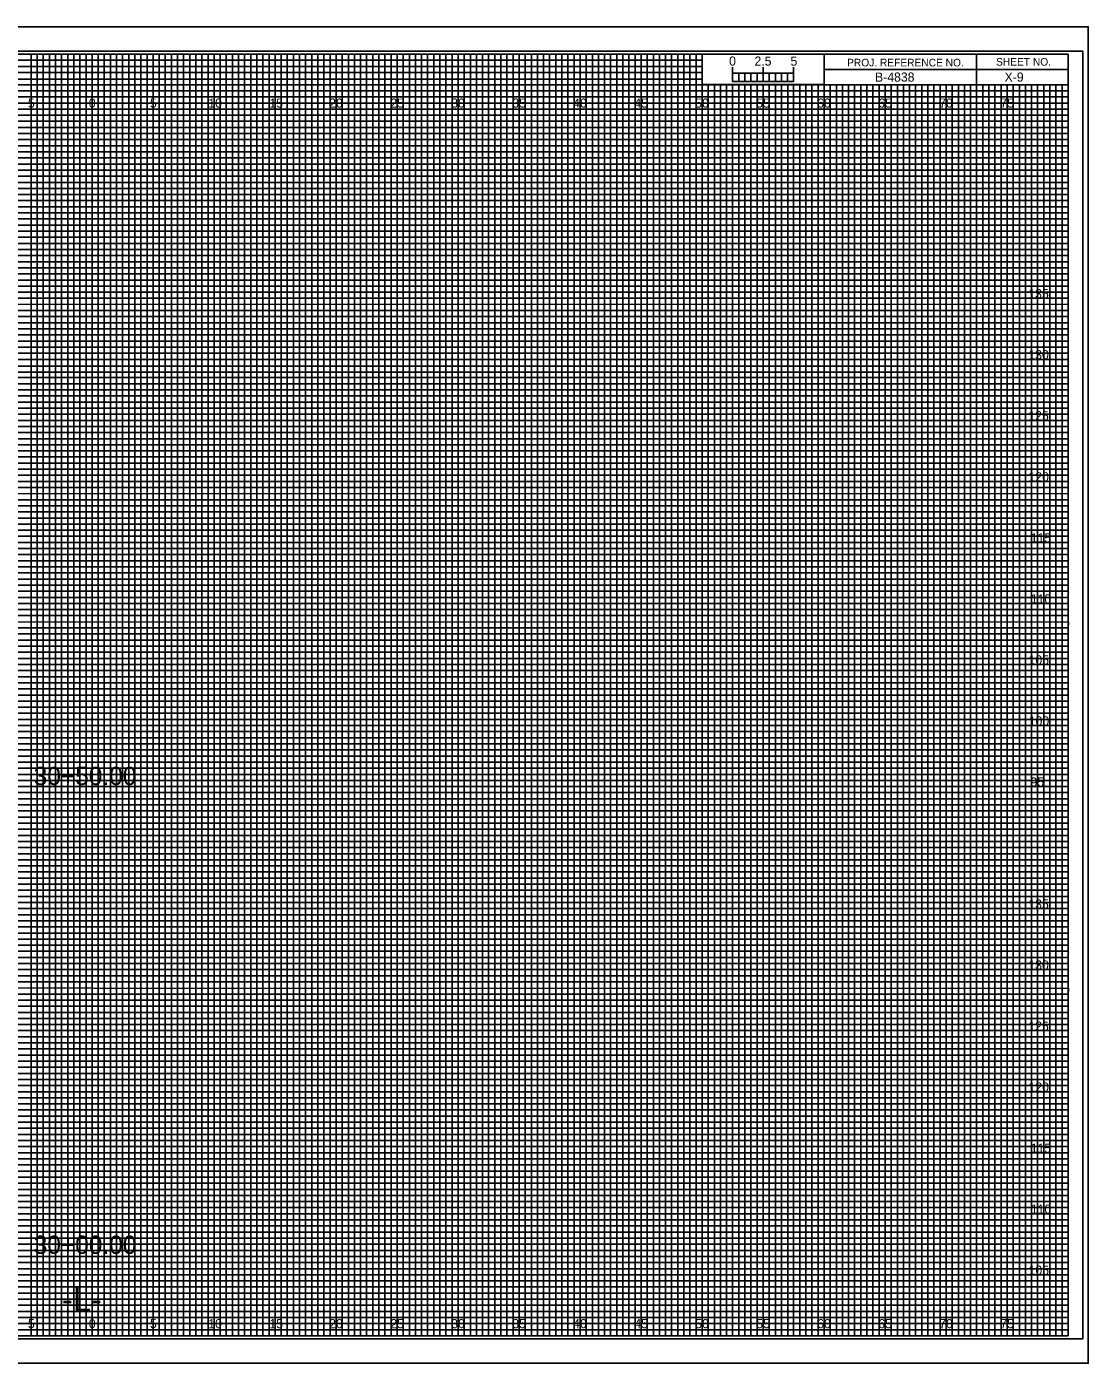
# Model space of a CAD drawing. Extents: x -7 to 182, y -2 to 1647.
# Drawn here: x 74.6 to 161.7, y 767.8 to 877.2 of the extents above; entities that cross this region are included whole.
import ezdxf

# ---------------------------------------------------------------- set-up
doc = ezdxf.new("R2010")
doc.units = 0
for name, color, linetype in [('Exist CMT Pavement', 7, 'Continuous'), ('Exist Cross Section Cell', 7, 'Continuous'), ('Exist XS Ground Line', 7, 'Continuous'), ('Prop CMT Pvmt Course 1', 7, 'Continuous'), ('Prop CMT Pvmt Course 2', 7, 'Continuous'), ('Prop CMT Pvmt Course 2 Wedge', 7, 'Continuous'), ('Prop CMT Pvmt Course 3', 7, 'Continuous'), ('Prop CMT Pvmt Surface', 7, 'Continuous'), ('Prop CMT Pvmt Surface Shoulder', 7, 'Continuous'), ('Prop CMT Pvmt Wedge Surface 1', 7, 'Continuous'), ('Prop CMT Pvmt Wedge Surface 2', 7, 'Continuous'), ('Prop CMT Pvmt Wedge Surface 3', 7, 'Continuous'), ('Prop CMT Shld Paved Course 1', 7, 'Continuous'), ('Prop CMT Shld Paved Course 2', 7, 'Continuous'), ('Prop CMT Shld Paved Course 3', 7, 'Continuous'), ('Prop CMT Slope Grass', 7, 'Continuous'), ('Prop CMT Subgrade Earthwork', 7, 'Continuous')]:
    doc.layers.add(name, color=color, linetype=linetype)

msp = doc.modelspace()

# ---------------------------------------------------------------- linework, layer by layer
at = {"layer": 'Exist XS Ground Line'}
for p, q in [((75, 875), (70, 875)), ((75, 770), (75, 875)), ((85, 875), (80, 875)), ((80, 875), (80, 770)), ((85, 770), (85, 875)), ((95, 875), (90, 875)), ((90, 875), (90, 770)), ((95, 770), (95, 875)), ((105, 875), (100, 875)), ((100, 875), (100, 770)), ((105, 770), (105, 875)), ((115, 875), (110, 875)), ((110, 875), (110, 770)), ((115, 770), (115, 875)), ((125, 875), (120, 875)), ((120, 875), (120, 770)), ((125, 770), (125, 875)), ((130, 875), (130, 770)), ((135, 770), (135, 872.5)), ((145, 872.5), (140, 872.5)), ((140, 872.5), (140, 770)), ((145, 770), (145, 872.5)), ((155, 872.5), (150, 872.5)), ((150, 872.5), (150, 770)), ((155, 770), (155, 872.5)), ((80, 770), (75, 770)), ((90, 770), (85, 770)), ((100, 770), (95, 770)), ((110, 770), (105, 770)), ((120, 770), (115, 770)), ((130, 770), (125, 770)), ((140, 770), (135, 770)), ((150, 770), (145, 770)), ((160, 770), (155, 770)), ((160, 770), (160, 770))]:
    msp.add_line(p, q, dxfattribs=at)
for points in [[(0, 870), (160, 870), (160, 865), (0, 865)], [(0, 860), (160, 860), (160, 855), (0, 855)], [(0, 850), (160, 850), (160, 845), (0, 845)], [(0, 840), (160, 840), (160, 835), (0, 835)], [(0, 830), (160, 830), (160, 825), (0, 825)], [(0, 820), (160, 820), (160, 815), (0, 815)], [(0, 810), (160, 810), (160, 805), (0, 805)], [(0, 800), (160, 800), (160, 795), (0, 795)], [(0, 790), (160, 790), (160, 785), (0, 785)], [(0, 780), (160, 780), (160, 775), (0, 775)]]:
    msp.add_lwpolyline(points, dxfattribs=at)
at = {"layer": 'Prop CMT Pvmt Course 2'}
for p, q in [((132.5, 872.75), (132.5, 873.95)), ((132.5, 873.45), (132.5, 873.95)), ((135, 872.75), (135, 873.95)), ((137.5, 872.75), (137.5, 873.95)), ((137.5, 873.45), (137.5, 873.95))]:
    msp.add_line(p, q, dxfattribs=at)
for points in [[(137.5, 873.45), (132.5, 873.45), (132.5, 872.75), (137.5, 872.75)], [(132.5, 873.45), (133, 873.45), (133, 872.75), (132.5, 872.75)], [(133.5, 873.45), (134, 873.45), (134, 872.75), (133.5, 872.75)], [(134.5, 873.45), (135, 873.45), (135, 872.75), (134.5, 872.75)], [(135.5, 873.45), (136, 873.45), (136, 872.75), (135.5, 872.75)], [(136.5, 873.45), (137, 873.45), (137, 872.75), (136.5, 872.75)]]:
    msp.add_lwpolyline(points, close=True, dxfattribs=at)
at = {"layer": 'Prop CMT Pvmt Course 3'}
msp.add_lwpolyline([(-6.7, 767.75), (161.65, 767.75), (161.65, 877.25), (-6.7, 877.25)], close=True, dxfattribs=at)
at = {"layer": 'Prop CMT Pvmt Wedge Surface 1'}
for p, q in [((0, 874.5), (130, 874.5)), ((130, 873.99), (0, 873.99)), ((130, 874.5), (130, 873.99)), ((0, 873.5), (130, 873.5)), ((130, 872.95), (0, 872.95)), ((130, 873.5), (130, 872.95)), ((0, 872), (160, 872))]:
    msp.add_line(p, q, dxfattribs=at)
for points in [[(0, 871.5), (135, 871.5), (160, 871.5), (160, 871), (0, 871)], [(0, 870.5), (160, 870.5), (160, 869.5), (0, 869.5)], [(0, 869), (160, 869), (160, 868.5), (0, 868.49)], [(0, 868), (160, 868), (160, 867), (0, 867)], [(0, 866.5), (160, 866.5), (160, 866), (0, 866)], [(0, 865.5), (160, 865.5), (160, 864.5), (0, 864.5)], [(0, 864), (160, 864), (160, 863.5), (0, 863.5)], [(0, 863), (160, 863), (160, 862), (0, 862)], [(0, 861.5), (160, 861.5), (160, 861), (0, 861)], [(0, 860.5), (160, 860.5), (160, 859.5), (0, 859.5)], [(0, 859), (160, 859), (160, 858.5), (0, 858.5)], [(0, 858), (160, 858), (160, 856.98), (160, 856.5), (160, 856), (0, 856)], [(0, 857), (160, 857), (160, 856.5), (0, 856.5)], [(0, 855.5), (160, 855.5), (160, 854.5), (0, 854.51)], [(0, 854.51), (160, 854.5), (160, 854), (0, 854)], [(0, 853.5), (160, 853.5), (160, 853), (0, 853)], [(0, 852), (160, 852), (160, 851.5), (0, 851.5)], [(0, 851), (160, 851), (160, 850.5), (0, 850.5)], [(-0.04, 849.45), (160, 849.45), (160, 848.94), (-0.04, 848.94)], [(0, 848.5), (160, 848.5), (160, 848), (0, 848)], [(0, 847), (160, 847), (160, 846.5), (0, 846.5)], [(0, 846), (160, 846), (160, 845.5), (0, 845.5)], [(0, 844.5), (160, 844.5), (160, 844), (0, 844)], [(0, 843.5), (160, 843.5), (160, 843), (0, 843)], [(0, 842), (160, 842), (160, 841.5), (0, 841.5)], [(0, 841), (160, 841), (160, 840.5), (0, 840.5)], [(0, 839.5), (160, 839.5), (160, 838.99), (0, 839)], [(0, 838.5), (160, 838.5), (160, 838), (0, 838)], [(0, 837), (160, 837), (160, 836.5), (0, 836.5)], [(0, 836), (160, 836), (160, 835.5), (0, 835.5)], [(0, 834.5), (160, 834.5), (160, 834), (0, 834)], [(0, 833.5), (160, 833.5), (160, 833), (0, 833)], [(0, 832), (160, 832), (160, 831.5), (0, 831.5)], [(0, 831), (160, 831), (160, 830.5), (0, 830.5)], [(0, 829.5), (160, 829.5), (160, 829), (0, 829)], [(0, 828.5), (160.03, 828.46), (160, 828), (0, 828)], [(0, 827), (160, 827), (160, 826.5), (0, 826.5)], [(0, 826), (160, 826), (160, 825.5), (0, 825.5)], [(0, 824.5), (160, 824.5), (160, 824), (0, 824)], [(0, 823.5), (160, 823.5), (160, 823), (0, 823)], [(0, 822), (160, 822), (160, 821.5), (0, 821.5)], [(0, 821), (160, 821), (160, 820.5), (0, 820.5)], [(0, 819.5), (160, 819.5), (160, 819), (0, 819)], [(0, 818.5), (160, 818.5), (160, 818), (0, 818)], [(0, 817), (160, 817), (160, 816.5), (0, 816.5)], [(0, 816), (160, 816), (160, 815.5), (0, 815.5)], [(0, 814.5), (160, 814.5), (160, 814), (0, 814)], [(0, 813.5), (160, 813.5), (160, 813), (0, 813)], [(0, 812), (160, 812), (160, 811.5), (0, 811.5)], [(0, 811), (160, 811), (160, 810.5), (0, 810.5)], [(0, 809.5), (160, 809.5), (160, 808.99), (0, 809)], [(0, 808.5), (160, 808.5), (160, 808), (0, 808)], [(0, 807), (160, 807), (160, 806.5), (0, 806.5)], [(0, 806), (160, 806), (160, 805.5), (0, 805.5)], [(0, 804.5), (160, 804.5), (160, 804), (0, 804)], [(0, 803.5), (160, 803.5), (160, 803), (0, 803)], [(0, 802), (160, 802), (160, 801.5), (0, 801.5)], [(0, 801), (160, 801), (160, 800.5), (0, 800.5)], [(0, 799.5), (160, 799.5), (160, 799), (0, 799)], [(0, 798.5), (160.03, 798.46), (160, 798), (0, 798)], [(0, 797), (160, 797), (160, 796.5), (0, 796.5)], [(0, 796), (160, 796), (160, 795.5), (0, 795.5)], [(0, 794.5), (160, 794.5), (160, 794), (0, 794)], [(0, 793.5), (160, 793.5), (160, 793), (0, 793)], [(0, 792), (160, 792), (160, 791.5), (0, 791.5)], [(0, 791), (160, 791), (160, 790.5), (0, 790.5)], [(0, 789.5), (160, 789.5), (160, 789), (0, 789)], [(0, 788.5), (160, 788.5), (160, 788), (0, 788)], [(0, 787), (160, 787), (160, 786.5), (0, 786.5)], [(0, 786), (160, 786), (160, 785.5), (0, 785.5)], [(0, 784.5), (160, 784.5), (160, 784), (0, 784)], [(0, 783.5), (160, 783.5), (160, 783), (0, 783)], [(0, 782), (160, 782), (160, 781.5), (0, 781.5)], [(0, 781), (160, 781), (160, 780.5), (0, 780.5)], [(0, 779.5), (160, 779.5), (160, 779), (0, 779)], [(0, 778.5), (160, 778.5), (160, 778), (0, 778)], [(0, 777), (160, 777), (160, 776.5), (0, 776.5)], [(0, 776), (160, 776), (160, 775.5), (0, 775.5)], [(0, 774.5), (160, 774.5), (160, 774), (0, 774)], [(0, 773.5), (160, 773.5), (160, 773), (0, 773)], [(0, 772), (160, 772), (160, 771.5), (0, 771.5)], [(0, 771), (160, 771), (160, 770.5), (0, 770.5)]]:
    msp.add_lwpolyline(points, dxfattribs=at)
at = {"layer": 'Prop CMT Pvmt Wedge Surface 2'}
for p, q in [((152.5, 875), (152.5, 872.5)), ((152.5, 872.5), (152.5, 875)), ((160, 873.75), (140, 873.75)), ((140, 873.75), (140, 872.5)), ((140, 872.5), (160, 872.5))]:
    msp.add_line(p, q, dxfattribs=at)
for points in [[(160, 875), (0, 875), (0, 770), (160, 770)], [(140, 875), (130, 875), (130, 872.51), (140, 872.51)], [(160, 875), (140, 875), (140, 872.5), (160, 872.5)]]:
    msp.add_lwpolyline(points, close=True, dxfattribs=at)
at = {"layer": 'Prop CMT Pvmt Wedge Surface 3'}
for p, q in [((133.5, 872.5), (133, 872.5)), ((133, 872.5), (133, 770)), ((133.5, 770), (133.5, 872.5)), ((134.5, 872.5), (134, 872.5)), ((134, 872.5), (134, 770)), ((134.5, 770), (134.5, 872.5)), ((133, 770), (132.5, 770)), ((134, 770), (133.5, 770))]:
    msp.add_line(p, q, dxfattribs=at)
for points in [[(75, 770), (75.5, 770), (75.5, 875), (76, 875), (76, 770)], [(76, 770), (76.5, 770), (76.5, 875), (77, 875), (77, 770)], [(77.5, 770), (78, 770), (78, 875), (78.5, 875), (78.5, 770)], [(78.5, 770), (79, 770), (79, 875), (79.5, 875), (79.5, 770)], [(80, 770), (80.5, 770), (80.5, 875), (81, 875), (81, 770)], [(81, 770), (81.5, 770), (81.5, 875), (82, 875), (82, 770)], [(82.5, 770), (83, 770), (83, 875), (83.5, 875), (83.5, 770)], [(83.5, 770), (84, 770), (84, 875), (84.5, 875), (84.5, 770)], [(85, 770), (85.5, 770), (85.5, 875), (86, 875), (86, 770)], [(86, 770), (86.5, 770), (86.5, 875), (87, 875), (87, 770)], [(87.5, 770), (88, 770), (88, 875), (88.5, 875), (88.5, 770)], [(88.5, 770), (89, 770), (89, 875), (89.5, 875), (89.5, 770)], [(90, 770), (90.5, 770), (90.5, 875), (91, 875), (91, 770)], [(91, 770), (91.5, 770), (91.5, 875), (92, 875), (92, 770)], [(92.5, 770), (93, 770), (93, 875), (93.5, 875), (93.5, 770)], [(93.5, 770), (94, 770), (94, 875), (94.5, 875), (94.5, 770)], [(95, 770), (95.5, 770), (95.5, 875), (96, 875), (96, 770)], [(96, 770), (96.5, 770), (96.5, 875), (97, 875), (97, 770)], [(97.5, 770), (98, 770), (98, 875), (98.5, 875), (98.5, 770)], [(98.5, 770), (99, 770), (99, 875), (99.5, 875), (99.5, 770)], [(100, 770), (100.5, 770), (100.5, 875), (101, 875), (101, 770)], [(101, 770), (101.5, 770), (101.5, 875), (102, 875), (102, 770)], [(102.5, 770), (103, 770), (103, 875), (103.5, 875), (103.5, 770)], [(103.5, 770), (104, 770), (104, 875), (104.5, 875), (104.5, 770)], [(105, 770), (105.5, 770), (105.5, 875), (106, 875), (106, 770)], [(106, 770), (106.5, 770), (106.5, 875), (107, 875), (107, 770)], [(107.5, 770), (108, 770), (108, 875), (108.5, 875), (108.5, 770)], [(108.5, 770), (109, 770), (109, 875), (109.5, 875), (109.5, 770)], [(110, 770), (110.5, 770), (110.5, 875), (111, 875), (111, 770)], [(111, 770), (111.5, 770), (111.5, 875), (112, 875), (112, 770)], [(112.5, 770), (113, 770), (113, 875), (113.5, 875), (113.5, 770)], [(113.5, 770), (114, 770), (114, 875), (114.5, 875), (114.5, 770)], [(115, 770), (115.5, 770), (115.5, 875), (116, 875), (116, 770)], [(116, 770), (116.5, 770), (116.5, 875), (117, 875), (117, 770)], [(117.5, 770), (118, 770), (118, 875), (118.5, 875), (118.5, 770)], [(118.5, 770), (119, 770), (119, 875), (119.5, 875), (119.5, 770)], [(120, 770), (120.5, 770), (120.5, 875), (121, 875), (121, 770)], [(121, 770), (121.5, 770), (121.5, 875), (122, 875), (122, 770)], [(122.5, 770), (123, 770), (123, 875), (123.5, 875), (123.5, 770)], [(123.5, 770), (124, 770), (124, 875), (124.5, 875), (124.5, 770)], [(125, 770), (125.5, 770), (125.5, 875), (126, 875), (126, 770)], [(126, 770), (126.5, 770), (126.5, 875), (127, 875), (127, 770)], [(127.5, 770), (128, 770), (128, 875), (128.5, 875), (128.5, 770)], [(128.5, 770), (129, 770), (129, 875), (129.5, 875), (129.5, 770)], [(130, 770), (130.5, 770), (130.5, 872.5), (131.01, 872.5), (131.01, 770)], [(131, 770), (131.5, 770), (131.5, 872.5), (132, 872.5), (132, 770)], [(135, 770), (135.49, 770), (135.49, 872.5), (136, 872.5), (136, 770)], [(136, 770), (136.5, 770), (136.5, 872.5), (137.03, 872.5), (137.03, 770)], [(137.5, 770), (138, 770), (138, 872.5), (138.5, 872.5), (138.5, 770)], [(138.5, 770), (139, 770), (139, 872.5), (139.5, 872.5), (139.5, 770)], [(140, 770), (140.5, 770), (140.5, 872.5), (141, 872.5), (141, 770)], [(141, 770), (141.5, 770), (141.5, 872.5), (142, 872.5), (142, 770)], [(142.5, 770), (143, 770), (143, 872.5), (143.5, 872.5), (143.5, 770)], [(143.5, 770), (144, 770), (144, 872.5), (144.5, 872.5), (144.5, 770)], [(145, 770), (145.5, 770), (145.5, 872.5), (146, 872.5), (146, 770)], [(146, 770), (146.5, 770), (146.5, 872.5), (147, 872.5), (147, 770)], [(147.5, 770), (148, 770), (148, 872.5), (148.5, 872.5), (148.5, 770)], [(148.5, 770), (149, 770), (149, 872.5), (149.5, 872.5), (149.5, 770)], [(150, 770), (150.5, 770), (150.5, 872.5), (151, 872.5), (151, 770)], [(151, 770), (151.5, 770), (151.5, 872.5), (152, 872.5), (152, 770)], [(152.5, 770), (153, 770), (153, 872.5), (153.5, 872.5), (153.5, 770)], [(153.5, 770), (154, 770), (154, 872.5), (154.5, 872.5), (154.5, 770)], [(155, 770), (155.5, 770), (155.5, 872.5), (156, 872.5), (156, 770)], [(156, 770), (156.5, 770), (156.5, 872.5), (157, 872.5), (157, 770)], [(157.5, 770), (158, 770), (158, 872.5), (158.5, 872.5), (158.5, 770)], [(158.5, 770), (159, 770), (159, 872.5), (159.5, 872.5), (159.5, 770)]]:
    msp.add_lwpolyline(points, dxfattribs=at)
at = {"layer": 'Prop CMT Shld Paved Course 1'}
for p, q in [((75, 770), (75, 875)), ((80, 770), (80, 875)), ((85, 770), (85, 875)), ((90, 770), (90, 875)), ((95, 770), (95, 875)), ((100, 770), (100, 875)), ((105, 770), (105, 875)), ((110, 770), (110, 875)), ((115, 770), (115, 875)), ((120, 770), (120, 875)), ((125, 770), (125, 875)), ((130, 770), (130, 872.34)), ((135, 770), (135, 872.34)), ((140, 770), (140, 872.34)), ((145, 770), (145, 872.34)), ((150, 770), (150, 872.34)), ((155, 770), (155, 872.34)), ((0, 870), (160, 870)), ((0, 865), (160, 865)), ((0, 860), (160, 860)), ((0, 855), (160, 855)), ((0, 850), (160, 850)), ((0, 845), (160, 845)), ((0, 840), (160, 840)), ((0, 835), (160, 835)), ((0, 830), (160, 830)), ((0, 825), (160, 825)), ((0, 820), (160, 820)), ((0, 815), (160, 815)), ((0, 810), (160, 810)), ((0, 805), (160, 805)), ((0, 800), (160, 800)), ((0, 795), (160, 795)), ((0, 790), (160, 790)), ((0, 785), (160, 785)), ((0, 780), (160, 780)), ((0, 775), (160, 775))]:
    msp.add_line(p, q, dxfattribs=at)
at = {"layer": 'Prop CMT Shld Paved Course 2'}
for p, q in [((161.65, 877.25), (-6.7, 877.25)), ((-6.7, 767.75), (161.65, 767.75))]:
    msp.add_line(p, q, dxfattribs=at)
at = {"layer": 'Prop CMT Slope Grass'}
msp.add_lwpolyline([(-5.4, 769.75), (161.2, 769.75), (161.2, 875.25), (-5.4, 875.25)], close=True, dxfattribs=at)
at = {"layer": 'Prop CMT Subgrade Earthwork'}
for points in [[(72.5, 770), (77.5, 770), (77.5, 875), (82.5, 875), (82.5, 770), (87.5, 770), (87.5, 875), (92.5, 875), (92.5, 770), (97.5, 770), (97.5, 875), (102.5, 875), (102.5, 770), (107.5, 770), (107.5, 875), (112.5, 875), (112.5, 770), (117.5, 770), (117.5, 875), (122.5, 875), (122.5, 770), (127.5, 770), (127.5, 875), (129.97, 875), (130, 875), (130, 872.5), (132.5, 872.5), (132.5, 770), (137.5, 770), (137.5, 872.5), (142.5, 872.5), (142.5, 770), (147.5, 770), (147.5, 872.5), (152.5, 872.5), (152.5, 770), (157.5, 770), (157.5, 872.5)], [(0, 872.5), (137.5, 872.5)], [(0, 862.5), (160, 862.5), (160, 867.5), (0, 867.5)], [(0, 852.5), (160, 852.5), (160, 857.5), (0, 857.5)], [(0, 842.5), (160, 842.5), (160, 847.5), (0, 847.5)], [(0, 832.5), (160, 832.5), (160, 837.5), (0, 837.5)], [(0, 822.5), (160, 822.5), (160, 827.5), (0, 827.5)], [(0, 812.5), (160, 812.5), (160, 817.5), (0, 817.5)], [(0, 802.5), (160, 802.5), (160, 807.5), (0, 807.5)], [(0, 792.5), (160, 792.5), (160, 797.5), (0, 797.5)], [(0, 782.5), (160, 782.5), (160, 787.5), (0, 787.5)], [(0, 772.5), (160, 772.5), (160, 777.5), (0, 777.5)]]:
    msp.add_lwpolyline(points, dxfattribs=at)

# ---------------------------------------------------------------- texts
at = {"layer": 'Exist CMT Pavement'}
for s, p in [('30+50.00', (75.21, 815.12)), ('30+00.00', (75.21, 776.71))]:
    msp.add_text(s, height=1.5, dxfattribs=at).set_placement(p)
at = {"layer": 'Exist Cross Section Cell'}
for s, p in [('5', (74.74, 870.62)), ('0', (79.73, 870.62)), ('0', (79.73, 870.62)), ('5', (84.74, 870.62)), ('10', (89.52, 870.62)), ('15', (94.53, 870.62)), ('20', (99.43, 870.62)), ('25', (104.44, 870.62)), ('30', (109.43, 870.62)), ('35', (114.44, 870.62)), ('40', (119.43, 870.62)), ('45', (124.44, 870.62)), ('50', (129.43, 870.62)), ('55', (134.44, 870.62)), ('60', (139.43, 870.62)), ('65', (144.44, 870.62)), ('70', (149.43, 870.62)), ('75', (154.44, 870.62)), ('5', (74.74, 770.62)), ('0', (79.73, 770.62)), ('0', (79.73, 770.62)), ('5', (84.74, 770.62)), ('10', (89.52, 770.62)), ('15', (94.53, 770.62)), ('20', (99.43, 770.62)), ('25', (104.44, 770.62)), ('30', (109.43, 770.62)), ('35', (114.44, 770.62)), ('40', (119.43, 770.62)), ('45', (124.44, 770.62)), ('50', (129.43, 770.62)), ('55', (134.44, 770.62)), ('60', (139.43, 770.62)), ('65', (144.44, 770.62)), ('70', (149.43, 770.62)), ('75', (154.44, 770.62))]:
    msp.add_text(s, height=0.75, dxfattribs=at).set_placement(p)
at = {"layer": 'Prop CMT Pvmt Course 1'}
msp.add_text('-L-', height=2, dxfattribs=at).set_placement((77.53, 772))
at = {"layer": 'Prop CMT Pvmt Course 2'}
msp.add_text('0', height=0.75, dxfattribs=at).set_placement((132.21, 874.06))
at = {"layer": 'Prop CMT Pvmt Course 2 Wedge'}
for s, p in [('2.5', (134.29, 874.06)), ('5', (137.24, 874.06))]:
    msp.add_text(s, height=0.75, dxfattribs=at).set_placement(p)
at = {"layer": 'Prop CMT Pvmt Surface'}
msp.add_text('X-9', height=0.75, dxfattribs=at).set_placement((154.79, 872.75))
at = {"layer": 'Prop CMT Pvmt Surface Shoulder'}
msp.add_text('B-4838', height=0.75, dxfattribs=at).set_placement((144.17, 872.75))
at = {"layer": 'Prop CMT Pvmt Wedge Surface 2'}
for s, p in [('PROJ. REFERENCE NO.', (141.88, 874)), ('SHEET NO.', (154.09, 874.06))]:
    msp.add_text(s, height=0.625, dxfattribs=at).set_placement(p)
at = {"layer": 'Prop CMT Shld Paved Course 3'}
for s, p in [('135', (156.74, 855)), ('130', (156.74, 850)), ('125', (156.74, 845)), ('120', (156.75, 840)), ('115', (156.93, 835)), ('110', (156.94, 830)), ('105', (156.76, 825)), ('100', (156.77, 820)), ('95', (156.92, 815)), ('135', (156.74, 805)), ('130', (156.74, 800)), ('125', (156.74, 795)), ('120', (156.75, 790)), ('115', (156.93, 785)), ('110', (156.94, 780)), ('105', (156.76, 775))]:
    msp.add_text(s, height=0.75, dxfattribs=at).set_placement(p)

doc.saveas('drawing.dxf')
